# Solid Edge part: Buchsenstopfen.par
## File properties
Author: heha
Template: Normal.par
Last saved by: heha
Revision: 8
Application: Solid Edge
Genauigkeit: 0,990
Teilflächenrmatvorlage: Model Default
Coef. of Thermal Exp: 0.0
Thermal Conductivity: 0.0
Specific Heat: 0.0
Modulus of Elasticity: 0.0
Poission's Ratio: 0.0
Yield Stress: 0.0
Ultimate Stress: 0.0
Elongation: 0.0
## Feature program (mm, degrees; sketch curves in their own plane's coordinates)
sketch for "unnamed Protrusion 1" plane through (0, 0, 0) normal (1, 0, 0) x-axis (0, 1, 0)
  line (-17.2, 9.2) -> (17.2, 9.2)
  line (17.2, 9.2) -> (17.2, -9.2)
  line (17.2, -9.2) -> (-17.2, -9.2)
  line (-17.2, -9.2) -> (-17.2, 9.2)
  dimension (linear) = 17.2
  dimension (linear) = 17.2
extrude "unnamed Protrusion 1" add finite 1 along -normal
fillet "Rund15" radius 1.5
sketch for "Stopfer" plane through (0, 0, 0) normal (1, 0, 0) x-axis (0, 1, 0)
  line (-10.1, 7) -> (10.1, 7)
  line (10.1, 7) -> (10.1, -7)
  line (10.1, -7) -> (-10.1, -7)
  line (-10.1, -7) -> (-10.1, 7)
  dimension (linear) = 10.1
  dimension (linear) = 10.1
extrude "Stopfer" add finite 9 along -normal
sketch for "unnamed Cutout 1" plane through (0, 0, 0) normal (0, 0, 1) x-axis (1, 0, 0)
  circle centre (-32.4, 0) radius 26
extrude "unnamed Cutout 1" cut through
sketch for "USB_B_Steckergehäuse" plane through (0, 0, 0) normal (1, 0, 0) x-axis (0, 1, 0)
  line (-5.9, 9.2) -> (5.9, 9.2)
  line (5.9, 9.2) -> (5.9, -1.8)
  line (5.9, -1.8) -> (-5.9, -1.8)
  line (-5.9, -1.8) -> (-5.9, 9.2)
  dimension (linear) = 5.9
  dimension (linear) = 5.9
extrude "USB_B_Steckergehäuse" cut finite 5 along -normal
sketch for "unnamed Cutout 2" plane through (0, 0, 0) normal (1, 0, 0) x-axis (0, 1, 0)
  line (-4.4, 7.3) -> (-4.4, -0.3)
  line (-4.4, -0.3) -> (4.4, -0.3)
  line (4.4, -0.3) -> (4.4, 7.3)
  line (4.4, 7.3) -> (-4.4, 7.3)
  dimension (linear) = 4.4
extrude "unnamed Cutout 2" cut through along -normal
chamfer "Druckschräge" setback 1
chamfer "Fase04" setback 0.5
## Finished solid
Body 1: solid body, 26 faces, 68 edges, 44 vertices.
  Faces by surface: plane 21, cylinder 5
  Edges by curve: line 56, circle 12
Bounding box of the edges (mm): 8.442 x 34.400 x 18.400, from (-8.4419, -17.2, -9.2) to (0, 17.2, 9.2).
Cylindrical faces by radius (mm): R1.5 x4, R26 x1
Planar faces by outward normal: +x 1, +y 4, +z 6, -x 1, -y 4, -z 2, oblique 3
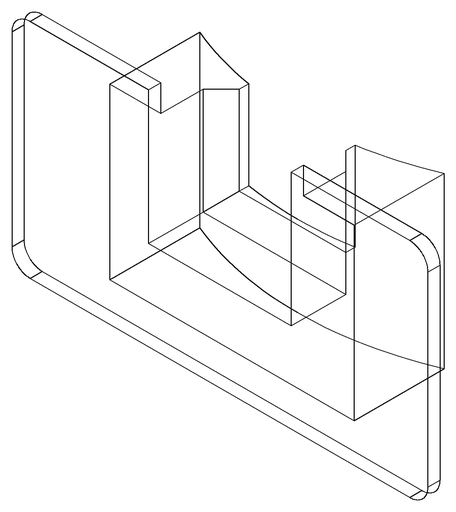
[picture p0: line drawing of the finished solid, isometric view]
